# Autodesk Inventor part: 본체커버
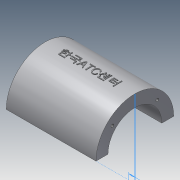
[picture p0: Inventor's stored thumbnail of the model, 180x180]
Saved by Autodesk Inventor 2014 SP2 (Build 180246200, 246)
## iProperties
Created: 2015-12
Part Number: 본체커버
Material: 알루미늄 6061
Document SubType Name: Modeling
Designer: mduedu
Density: 2.71 g/cm^3
Mass: 174.994 g
Surface Area: 167.085 cm^2
Volume: 64.5736 cm^3
Appearance: 알루미늄 - 평지
Author: mduedu
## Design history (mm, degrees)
sketch "스케치1"
  geometry: L1 (45, 40)-(-45, 40); L2 (-45, 40)-(-45, -40); L3 (-45, -40)-(45, -40); L4 (45, -40)-(45, 40); L5 (45, 40)-(-45, -40); L6 (-45, 40)-(45, -40); 1 further point
  constraints: 12 end point, 2 midpoint, 2 parallel, 1 horizontal, 1 perpendicular
  dimensions: "d0" = 90 distance of L2.end L3.end; "d2" = 80 distance of L1.end L2.end
extrude "돌출1" new body sketch "스케치1" distance "d3" = 10; taper "d4" = 0 deg
sketch "스케치2"
  geometry: L1 (0, 40)-(0, -40) reference; C1 r 32.5 at (80, 0); 1 further point
  constraints: 1 centre point
  dimensions: "d5" = 65 diameter of C1; "d6" = 80 distance from line of C1.centre L1
extrude "돌출2" join sketch "스케치2" stored distance "d7" = 75; taper "d8" = 0 deg
sketch "스케치3"
  geometry: L1 (-27.5, -20)-(27.5, -20); L2 (27.5, -20)-(27.5, 20); L3 (27.5, 20)-(-27.5, 20); L4 (-27.5, 20)-(-27.5, -20); L5 (-27.5, -20)-(27.5, 20); L6 (27.5, -20)-(-27.5, 20); 1 further point
  constraints: 12 end point, 2 midpoint, 2 parallel, 1 horizontal, 1 perpendicular
  dimensions: "d9" = 55 distance of L2.end L3.end; "d11" = 40 distance of L1.end L2.end
extrude "돌출3" new body sketch "스케치3" stored distance "d12" = 75; taper "d13" = 0 deg
fillet "모깎기1"
fillet "모깎기2"
feature "결합1"
  node "솔리드2"
fillet "모깎기3" dims "d14" = 10
sketch "스케치4"
  geometry: L1 (-37.5, 47.5)-(37.5, 47.5) reference; L2 (35, 10)-(45, 10) reference; L3 (32.5, 47.5)-(40, 10); L4 (37.5, 47.5)-(37.5, 112.5) reference; L5 (45, 10)-(45, 0) reference; 1 further point
  constraints: 2 end point, 1 midpoint, 1 point on line
  dimensions: "d15" = 5 distance from line of L3.start L4; "d16" = 5 distance from line of L3.end L5
sketch "스케치5"
  geometry: L1 (10, 40)-(10, 30) reference; L2 (10, 35)-(56.569, 22.522); L3 (0, 40)-(10, 40) reference; 2 further points
  constraints: 2 end point, 1 midpoint, 2 other
  dimensions: "d17" = 5 distance from line of L2.start L3; "d18" = 15 deg angle of L2 L3
feature "리브1" dims "d19" = 1, "d20" = 6, "d21" = 0, "d22" = 0, "d23" = 1, "d24" = 1
feature "리브2" dims "d25" = 1, "d26" = 6, "d27" = 0, "d28" = 0, "d29" = 1, "d30" = 1
fillet "모깎기4" dims "d31" = 2
fillet "모깎기5" dims "d32" = 2
fillet "모깎기6" dims "d33" = 2
sketch "스케치6"
  geometry: A1 r 10 centre (-35, 30) between (-35, 40) and (-45, 30) reference; A2 r 10 centre (35, 30) between (45, 30) and (35, 40) reference; A3 r 10 centre (35, -30) between (35, -40) and (45, -30) reference; A4 r 10 centre (-35, -30) between (-45, -30) and (-35, -40) reference; 5 further points
  constraints: 4 coincident
hole "구멍1" sketch "스케치6" at (-35, 30), (35, 30), (35, -30), (-35, -30) diameter "d34" = 7; stored, may be unused: countersink angle "d38" = 90 deg, drill point angle "d40" = 118 deg; dims "d35" = 6, "d36" = 12, "d37" = 3, "d39" = 8
fillet "모깎기7" dims "d41" = 2
hole "구멍2" diameter "d44" = 45; stored, may be unused: countersink angle "d48" = 90 deg, drill point angle "d50" = 118 deg; dims "d42" = 10, "d43" = 10, "d45" = 6, "d46" = 4, "d47" = 2, "d49" = 8
sketch "스케치7" dims "d52" = 26.5
  geometry: L1 (0, 0)-(32.5, 0); L2 (0, 0)-(22.981, 22.981); A1 r 32.5 centre (0, 0) between (32.5, 0) and (22.981, 22.981) reference; 3 further points
  constraints: 4 end point, 2 point on circle, 1 coincident, 1 horizontal, 1 point on line, 3 other
  dimensions: "d51" = 45 deg angle of L2 L1
hole "구멍3" sketch "스케치7" at (18.738, 18.738) diameter "d54" = 2.459; stored, may be unused: countersink angle "d58" = 90 deg, drill point angle "d60" = 118 deg; dims "d55" = 8, "d56" = 4, "d57" = 2, "d59" = 10
sketch "스케치13"
  geometry: L1 (-45, 80)-(105, 80); L2 (105, 80)-(105, -30); L3 (105, -30)-(-45, -30); L4 (-45, -30)-(-45, 80); L5 (0, 0)-(60, 0) reference; C1 r 32.5 at (30, 80) reference; 1 further point
  constraints: 8 end point, 2 parallel, 1 coincident, 1 horizontal, 1 midpoint, 1 perpendicular
  dimensions: "d99" = 30 distance between parallel lines of L3 L5; "d126" = 150 distance between parallel lines of L2 L4
extrude "돌출8" cut sketch "스케치13" stored distance "d97" = 10; taper "d98" = 0 deg
node "작업 평면2"
sketch "스케치14"
  geometry: 2 further points
  constraints: 1 coincident, 1 other
feature "엠보싱1" sketch "스케치14" dims "d102" = 0.5, "d103" = 0
sketch "스케치18"
  geometry: L1 (0, -10)-(0, 0) reference; L2 (75, 0)-(75, -10) reference; L3 (0, -5)-(75, -5); C1 r 1.5 at (13, -5); 1 further point
  constraints: 2 end point, 2 midpoint, 1 centre point, 1 point on line
  dimensions: "d127" = 3 diameter of C1; "d128" = 13 distance from line of L1 C1.centre
extrude "돌출9" cut sketch "스케치18" distance "d129" = 2; taper "d130" = 0 deg
chamfer "모따기2" distance "d131" = 0.5; stored, may be unused: second distance "d132" = 2, angle "d133" = 45 deg
fillet "모깎기12" dims "d134" = 0.1
node "솔리드1"
mirror "대칭1"
mirror "대칭2"
pattern_circular "원형 패턴1" dims angle "d62" = 360 deg
mirror "대칭3"
mirror "대칭5"
mirror "대칭6"
